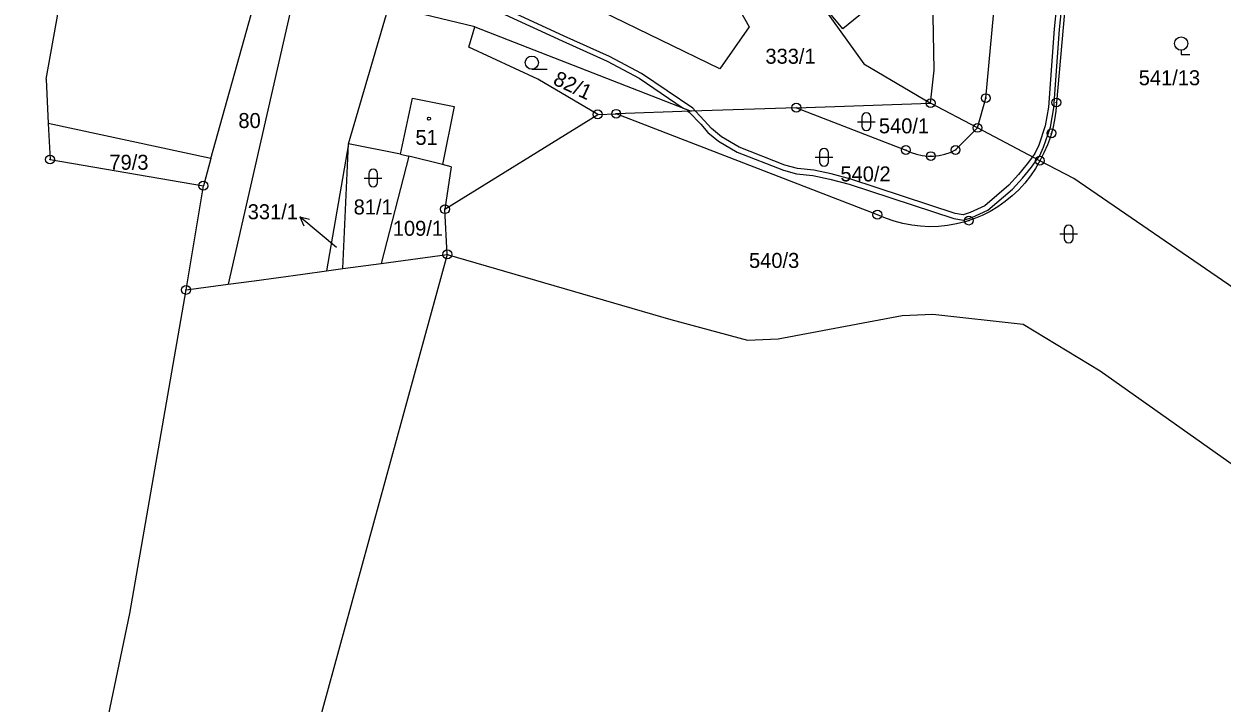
# Model space of a CAD drawing. Extents: x -759947 to -757003, y -1019641 to -1017100.
# Drawn here: x -758050.2 to -757914.5, y -1019281.8 to -1019204.8 of the extents above; entities that cross this region are included whole.
import ezdxf
from ezdxf.enums import TextEntityAlignment as Align

# ---------------------------------------------------------------- set-up
doc = ezdxf.new("R2010")
doc.units = 0
doc.header["$LTSCALE"] = 0.68
for name, color, linetype, lineweight in [('1', 7, 'Continuous', 25), ('13', 7, 'Continuous', 13), ('3', 7, 'Continuous', 25), ('4', 7, 'Continuous', 13), ('5', 7, 'Continuous', 25), ('7', 7, 'Continuous', 13), ('8', 7, 'Continuous', 25)]:
    doc.layers.add(name, color=color, linetype=linetype, lineweight=lineweight)
doc.layers.add('2', color=7, linetype='Continuous')

msp = doc.modelspace()

# ---------------------------------------------------------------- linework, layer by layer
at = {"layer": '1'}
for p, q in [((-757941.23, -1019213.24), (-757936.99, -1019167.01)), ((-758047.67, -1019211.1), (-758043.56, -1019188.24)), ((-758016.54, -1019188.18), (-758027.04, -1019234.34)), ((-757931.34, -1019192.98), (-757933.24, -1019213.74)), ((-757947.07, -1019210.08), (-757947.31, -1019197.72)), ((-757960.98, -1019201.07), (-757955.05, -1019209.35)), ((-758013.42, -1019218.43), (-758008.86, -1019202.82)), ((-757999.1, -1019205.15), (-758008.86, -1019202.82)), ((-757969.64, -1019202.3), (-757968.05, -1019205.15)), ((-758028.99, -1019220.09), (-758024.45, -1019203.75)), ((-757971.34, -1019209.93), (-757984.72, -1019203.42)), ((-757999.78, -1019207.45), (-757999.1, -1019205.15)), ((-757999.1, -1019205.15), (-757974.62, -1019214.73)), ((-757968.05, -1019205.15), (-757971.34, -1019209.93)), ((-757991.97, -1019211.08), (-757999.78, -1019207.45)), ((-757955.05, -1019209.35), (-757947.48, -1019213.82)), ((-758047.67, -1019211.1), (-758047.42, -1019216.11)), ((-757985.19, -1019215.09), (-757991.97, -1019211.08)), ((-757947.48, -1019213.82), (-757947.07, -1019210.08)), ((-757962.69, -1019214.33), (-757947.48, -1019213.82)), ((-757942.17, -1019216.62), (-757947.48, -1019213.82)), ((-757942.17, -1019216.62), (-757941.23, -1019213.24)), ((-758002.49, -1019225.84), (-757985.19, -1019215.09)), ((-757985.19, -1019215.09), (-757983.1, -1019215.02)), ((-757974.62, -1019214.73), (-757983.1, -1019215.02)), ((-757953.51, -1019226.46), (-757983.1, -1019215.02)), ((-757962.69, -1019214.33), (-757974.62, -1019214.73)), ((-757962.69, -1019214.33), (-757950.28, -1019219.13)), ((-758047.42, -1019216.11), (-758047.22, -1019220.2)), ((-758028.99, -1019220.09), (-758047.42, -1019216.11)), ((-757944.66, -1019219.12), (-757942.17, -1019216.62)), ((-757935.11, -1019220.34), (-757942.17, -1019216.62)), ((-758013.42, -1019218.43), (-758015.9, -1019232.82)), ((-758014.04, -1019232.57), (-758013.42, -1019218.43)), ((-758007.53, -1019219.6), (-758013.42, -1019218.43)), ((-758047.22, -1019220.2), (-758029.85, -1019223.17)), ((-758028.99, -1019220.09), (-758029.85, -1019223.17)), ((-758006.59, -1019219.83), (-758009.71, -1019231.98)), ((-758007.53, -1019219.6), (-758006.59, -1019219.83)), ((-758002.76, -1019220.76), (-758006.59, -1019219.83)), ((-757931.26, -1019222.37), (-757935.11, -1019220.34)), ((-758001.78, -1019221.02), (-758002.76, -1019220.76)), ((-758001.78, -1019221.02), (-758002.49, -1019225.84)), ((-758031.81, -1019234.99), (-758029.85, -1019223.17)), ((-757913.12, -1019234.84), (-757931.26, -1019222.37)), ((-758002.22, -1019230.96), (-758002.49, -1019225.84)), ((-758002.22, -1019230.96), (-758029.61, -1019330.91)), ((-758009.71, -1019231.98), (-758002.22, -1019230.96)), ((-758002.22, -1019230.96), (-757976.91, -1019238.33)), ((-758018.58, -1019233.19), (-758015.9, -1019232.82)), ((-758015.9, -1019232.82), (-758014.04, -1019232.57)), ((-758014.04, -1019232.57), (-758009.71, -1019231.98)), ((-758027.04, -1019234.34), (-758024.09, -1019233.94)), ((-758024.09, -1019233.94), (-758018.58, -1019233.19)), ((-758038.18, -1019271.68), (-758031.81, -1019234.99)), ((-758031.81, -1019234.99), (-758027.04, -1019234.34)), ((-757976.91, -1019238.33), (-757968.23, -1019240.67)), ((-757964.74, -1019240.55), (-757950.72, -1019237.9)), ((-757950.72, -1019237.9), (-757947.24, -1019237.75)), ((-757947.24, -1019237.75), (-757936.99, -1019238.86)), ((-757968.23, -1019240.67), (-757964.74, -1019240.55)), ((-758050.17, -1019328.93), (-758038.18, -1019271.68))]:
    msp.add_line(p, q, dxfattribs=at)
for points in [[(-757933.24, -1019213.74), (-757933.31, -1019214.727), (-757933.447, -1019215.706), (-757933.651, -1019216.674), (-757933.921, -1019217.626), (-757934.255, -1019218.557), (-757934.652, -1019219.463), (-757935.11, -1019220.34)], [(-757950.28, -1019219.13), (-757949.69, -1019219.4), (-757949.074, -1019219.605), (-757948.439, -1019219.743), (-757947.793, -1019219.812), (-757947.144, -1019219.811), (-757946.499, -1019219.74), (-757945.865, -1019219.6), (-757945.249, -1019219.392), (-757944.66, -1019219.12)], [(-757935.11, -1019220.34), (-757935.617, -1019221.225), (-757936.187, -1019222.071), (-757936.818, -1019222.873), (-757937.505, -1019223.627), (-757938.245, -1019224.328), (-757939.034, -1019224.974), (-757939.869, -1019225.561), (-757940.744, -1019226.085), (-757941.654, -1019226.545), (-757942.596, -1019226.936), (-757943.564, -1019227.258), (-757944.553, -1019227.509), (-757945.557, -1019227.687), (-757946.572, -1019227.791), (-757947.592, -1019227.821), (-757948.611, -1019227.776), (-757949.624, -1019227.657), (-757950.626, -1019227.465), (-757951.611, -1019227.201), (-757952.574, -1019226.865), (-757953.51, -1019226.46)], [(-757936.99, -1019238.86), (-757928.26, -1019244.15), (-757888.29, -1019272.47)]]:
    msp.add_lwpolyline(points, dxfattribs=at)
at = {"layer": '13'}
for points in [[(-757995.71, -1019203.78), (-757989.21, -1019206.76), (-757984.13, -1019209.07), (-757980.51, -1019210.97), (-757975.49, -1019214.39), (-757974.62, -1019214.73), (-757974.97, -1019214.74), (-757974.83, -1019214.84), (-757973.52, -1019216.21), (-757972.73, -1019217.14), (-757971.49, -1019218.12), (-757969.41, -1019219.36), (-757964.16, -1019221.42), (-757962.66, -1019221.81), (-757960.81, -1019222.03), (-757958.89, -1019222.42), (-757956.71, -1019223), (-757944.86, -1019226.91), (-757943.74, -1019227.09), (-757942.8, -1019226.76), (-757941.01, -1019225.96), (-757938.21, -1019223.57), (-757937.07, -1019222.32), (-757936.05, -1019221.07), (-757935.42, -1019220.18), (-757935.16, -1019219.81), (-757934.68, -1019218.8), (-757933.92, -1019216.53), (-757933.52, -1019214.35), (-757932.88, -1019205.46), (-757932.37, -1019200.28)], [(-757932.97, -1019200.22), (-757933.48, -1019205.4), (-757934.12, -1019214.27), (-757934.5, -1019216.39), (-757935.24, -1019218.58), (-757935.68, -1019219.51), (-757935.95, -1019219.9), (-757936.53, -1019220.71), (-757937.53, -1019221.92), (-757938.63, -1019223.13), (-757941.33, -1019225.44), (-757943.02, -1019226.2), (-757943.8, -1019226.47), (-757944.72, -1019226.33), (-757956.53, -1019222.42), (-757958.75, -1019221.84), (-757960.71, -1019221.43), (-757962.54, -1019221.21), (-757963.98, -1019220.84), (-757969.15, -1019218.82), (-757971.15, -1019217.62), (-757972.31, -1019216.7), (-757973.08, -1019215.81), (-757974.12, -1019214.71), (-757974.43, -1019214.38), (-757980.21, -1019210.45), (-757983.87, -1019208.53), (-757988.97, -1019206.22), (-757995.43, -1019203.24)]]:
    msp.add_lwpolyline(points, dxfattribs=at)
at = {"layer": '3'}
for p, q in [((-757992.653, -1019209.97), (-757990.903, -1019209.97)), ((-757955.761, -1019215.921), (-757953.759, -1019215.921)), ((-757955.261, -1019215.421), (-757955.261, -1019216.422)), ((-757954.259, -1019216.422), (-757954.259, -1019215.421)), ((-757960.551, -1019219.951), (-757958.549, -1019219.951)), ((-757960.051, -1019219.451), (-757960.051, -1019220.452)), ((-757959.049, -1019220.452), (-757959.049, -1019219.451)), ((-758011.121, -1019221.811), (-758011.121, -1019222.812)), ((-758010.119, -1019222.812), (-758010.119, -1019221.811)), ((-758011.621, -1019222.311), (-758009.619, -1019222.311)), ((-757932.851, -1019228.641), (-757930.849, -1019228.641)), ((-757932.351, -1019228.141), (-757932.351, -1019229.142)), ((-757931.349, -1019229.142), (-757931.349, -1019228.141))]:
    msp.add_line(p, q, dxfattribs=at)
msp.add_lwpolyline([(-757919.11, -1019207.812), (-757919.11, -1019208.31), (-757918.109, -1019208.31)], dxfattribs=at)
for centre in [(-757919.1093, -1019207.0609), (-757992.6529, -1019209.2198)]:
    msp.add_circle(centre, 0.75, dxfattribs=at)
for centre, start, end in [((-757954.76, -1019215.4209), 0, 180), ((-757954.76, -1019216.4209), 180, 359.98789), ((-757959.55, -1019219.4509), 0, 180), ((-757959.55, -1019220.4509), 180, 359.98789), ((-758010.62, -1019221.8109), 0, 180), ((-758010.62, -1019222.8109), 180, 359.98789), ((-757931.85, -1019228.1409), 0, 180), ((-757931.85, -1019229.1409), 180, 359.98789)]:
    msp.add_arc(centre, 0.5, start, end, dxfattribs=at)
at = {"layer": '4'}
for p, q in [((-757957.42, -1019205.39), (-757960.98, -1019201.07)), ((-757955.02, -1019203.42), (-757957.42, -1019205.39)), ((-758007.53, -1019219.6), (-758006.15, -1019213.25)), ((-758006.15, -1019213.25), (-758001.45, -1019214.19)), ((-758001.45, -1019214.19), (-758002.76, -1019220.76))]:
    msp.add_line(p, q, dxfattribs=at)
at = {"layer": '5'}
msp.add_circle((-758004.2968, -1019215.5792), 0.175, dxfattribs=at)
at = {"layer": '7'}
msp.add_line((-758018.919, -1019226.691), (-758018.474, -1019227.718), dxfattribs=at)
msp.add_lwpolyline([(-758014.78, -1019230.19), (-758016.62, -1019228.62), (-758018.919, -1019226.691), (-758017.83, -1019226.951)], dxfattribs=at)
at = {"layer": '8'}
for centre, radius in [((-757962.69, -1019214.3299), 0.5), ((-757947.48, -1019213.8199), 0.5), ((-757947.48, -1019213.8199), 0.0303), ((-757941.23, -1019213.2399), 0.5), ((-757941.23, -1019213.2399), 0.0303), ((-757933.24, -1019213.7399), 0.5), ((-757933.24, -1019213.7399), 0.0303), ((-757985.19, -1019215.0899), 0.5), ((-757985.19, -1019215.0899), 0.0303), ((-757983.1, -1019215.0199), 0.5), ((-757983.1, -1019215.0199), 0.0303), ((-757962.69, -1019214.3299), 0.0303), ((-757942.17, -1019216.6199), 0.5), ((-757942.17, -1019216.6199), 0.0303), ((-757933.8, -1019217.2299), 0.5), ((-757933.8, -1019217.2299), 0.0303), ((-757950.28, -1019219.1299), 0.5), ((-757950.28, -1019219.1299), 0.0303), ((-757947.46, -1019219.8199), 0.5), ((-757944.66, -1019219.1199), 0.5), ((-757944.66, -1019219.1199), 0.0303), ((-758047.22, -1019220.1999), 0.5), ((-758047.22, -1019220.1999), 0.0303), ((-757947.46, -1019219.8199), 0.0303), ((-757935.11, -1019220.3399), 0.5), ((-757935.11, -1019220.3399), 0.0303), ((-758029.85, -1019223.1699), 0.5), ((-758029.85, -1019223.1699), 0.0303), ((-758002.49, -1019225.8399), 0.5), ((-758002.49, -1019225.8399), 0.0303), ((-757953.51, -1019226.4599), 0.5), ((-757953.51, -1019226.4599), 0.0303), ((-757943.15, -1019227.1299), 0.5), ((-757943.15, -1019227.1299), 0.0303), ((-758002.22, -1019230.9599), 0.5), ((-758002.22, -1019230.9599), 0.0303), ((-758031.81, -1019234.9899), 0.5), ((-758031.81, -1019234.9899), 0.0303)]:
    msp.add_circle(centre, radius, dxfattribs=at)

# ---------------------------------------------------------------- texts
at = {"layer": '2'}
for s, p in [('333/1', (-757963.35, -1019209.345)), ('80', (-758024.619, -1019216.635)), ('51', (-758004.569, -1019218.545)), ('79/3', (-758038.279, -1019221.365)), ('81/1', (-758010.619, -1019226.435)), ('109/1', (-758005.55, -1019228.855))]:
    msp.add_text(s, height=1.7, dxfattribs=at).set_placement(p, align=Align.CENTER)
msp.add_text('82/1', height=1.7, rotation=335, dxfattribs=at).set_placement((-757988.3557, -1019212.5696), align=Align.CENTER)
for s, p in [('541/13', (-757923.91, -1019211.785)), ('540/1', (-757953.34, -1019217.235)), ('540/2', (-757957.7, -1019222.685)), ('540/3', (-757968.05, -1019232.495))]:
    msp.add_text(s, height=1.7, dxfattribs=at).set_placement(p)
msp.add_text('331/1', height=1.7, dxfattribs=at).set_placement((-758019.14, -1019226.975), align=Align.RIGHT)

doc.saveas('drawing.dxf')
